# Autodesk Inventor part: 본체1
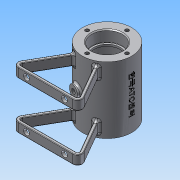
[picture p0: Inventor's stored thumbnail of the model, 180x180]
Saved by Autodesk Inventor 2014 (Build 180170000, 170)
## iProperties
Created: 2016-03
Part Number: 본체1
Material: 알루미늄 6061
Document SubType Name: Modeling
Designer: NET
Density: 2.71 g/cm^3
Appearance: 알루미늄 - 평지
Mass: 209.662 g
Surface Area: 328.168 cm^2
Volume: 77.3661 cm^3
Author: NET
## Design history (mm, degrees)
sketch "스케치1"
  geometry: C1 r 26 at (0, 0); 1 further point
  constraints: 1 centre point, 1 coincident
  dimensions: "d0" = 52 diameter of C1
extrude "돌출1" new body sketch "스케치1" stored distance "d1" = 70; taper "d2" = 0 deg
node "작업 평면2"
sketch "스케치2"
  geometry: 1 further point
sketch "스케치3"
  geometry: L1 (0, 0)-(0, -65); L2 (0, 0)-(58.644, 0); L3 (0, -65)-(-37.528, -65); L4 (-37.528, -65)-(37.528, -65); L5 (-32.332, -62)-(32.332, -62); L6 (11.547, -20)-(37.528, -65); L7 (-9.815, -23)-(-32.332, -62); L8 (32.332, -62)-(9.815, -23); L9 (-11.547, -20)-(-37.528, -65); L10 (-11.547, -20)-(11.547, -20); L11 (9.815, -23)-(-9.815, -23); C1 r 26 at (0, 0) reference; 2 further points
  constraints: 22 end point, 2 midpoint, 2 parallel, 1 horizontal, 1 point on line, 1 vertical
  dimensions: "d4" = 65 distance of L1.end L1.start; "d10" = 3 distance between parallel lines of L4 L5; "d13" = 3 distance between parallel lines of L11 L10; "d14" = 3 distance between parallel lines of L6 L8; "d15" = 3 distance between parallel lines of L9 L7; "d16" = 42 distance between parallel lines of L5 L10; "d17" = 51.96152 distance of L6.start L4.end; "d18" = 60 deg angle of L8 L7; "d19" = 75.05553 distance of L3.end L4.end
extrude "돌출2" join sketch "스케치3" distance "d20" = 10; taper "d21" = 0 deg
fillet "모깎기1" dims "d22" = 5
fillet "모깎기2" dims "d23" = 2
sketch "스케치4"
  geometry: C1 r 26 at (0, 0) reference; C2 r 16 at (0, 0)
  constraints: 1 centre point, 1 coincident
  dimensions: "d24" = 32 diameter of C2
extrude "돌출3" cut sketch "스케치4" distance "d25" = 12; taper "d26" = 0 deg
sketch "스케치5"
  geometry: C1 r 16 at (0, 0) reference; C2 r 14 at (0, 0)
  constraints: 1 centre point, 1 coincident
  dimensions: "d27" = 28 diameter of C2
extrude "돌출4" cut sketch "스케치5" distance "d28" = 2; taper "d29" = 0 deg
node "작업 평면4"
fillet "모깎기3" dims "d33" = 0.3
node "작업 평면5"
sketch "스케치7"
  geometry: C1 r 21 at (0, 0); 1 further point
  constraints: 1 centre point, 1 coincident
  dimensions: "d37" = 42 diameter of C1
extrude "돌출6" cut sketch "스케치7" stored distance "d38" = 42; taper "d39" = 0 deg
fillet "모깎기7" dims "d40" = 3
fillet "모깎기8" dims "d41" = 0.3
node "작업 평면6"
sketch "스케치8"
  geometry: C1 r 5 at (0, 0); 1 further point
  constraints: 1 centre point, 1 coincident
  dimensions: "d43" = 10 diameter of C1
extrude "돌출7" join sketch "스케치8" stored distance "d44" = 42; taper "d45" = 0 deg
sketch "스케치9"
  geometry: L1 (0, 0)-(7.506, -28.012); L2 (0, 0)-(0, -26); 2 further points
  constraints: 4 end point, 1 coincident, 1 vertical, 1 vertical alignment, 1 other
  dimensions: "d46" = 15 deg angle of L1 L2; "d47" = 29 distance of L1.start L1.end
node "작업 평면7"
sketch "스케치10"
  geometry: C1 r 6 at (0, 0); 1 further point
  constraints: 1 centre point, 1 coincident
  dimensions: "d48" = 12 diameter of C1
extrude "돌출8" join sketch "스케치10" stored distance "d49" = 42; taper "d50" = 0 deg
hole "구멍1" diameter "d53" = 5.188; stored, may be unused: countersink angle "d57" = 90 deg, drill point angle "d59" = 118 deg; dims "d51" = 10, "d52" = 10, "d54" = 10, "d55" = 4, "d56" = 2, "d58" = 10
hole "구멍2" diameter "d62" = 5.188; stored, may be unused: countersink angle "d66" = 90 deg, drill point angle "d68" = 118 deg; dims "d60" = 10, "d61" = 10, "d63" = 10, "d64" = 4, "d65" = 2, "d67" = 10
fillet "모깎기9" dims "d69" = 2
fillet "모깎기10" dims "d70" = 2
fillet "모깎기11" dims "d71" = 2
fillet "모깎기12" dims "d72" = 5
sketch "스케치11"
  geometry: L1 (0, 0)-(57.735, 0) reference; L2 (57.735, 10)-(0, 10) reference; L3 (28.868, 10)-(28.868, 0); C1 r 3 at (8.868, 5); C2 r 3 at (48.868, 5); 1 further point
  constraints: 2 centre point, 2 end point, 2 midpoint, 1 horizontal alignment
  dimensions: "d73" = 6 diameter of C1; "d74" = 6 diameter of C2; "d75" = 20 distance from line of C1.centre L3; "d76" = 40 distance of C2.centre C1.centre; "d77" = 5 distance from line of L1 C1.centre
extrude "돌출9" cut sketch "스케치11" distance "d78" = 42; taper "d79" = 0 deg
node "작업 평면8"
sketch "스케치12"
  geometry: L1 (26, 35)-(-26, 35) reference; 2 further points
  constraints: 1 coincident, 1 other
feature "엠보싱1" sketch "스케치12" dims "d82" = 0.5, "d83" = 0
chamfer "모따기1" distance "d84" = 1; stored, may be unused: second distance "d85" = 2, angle "d86" = 45 deg
chamfer "모따기2" distance "d87" = 1; stored, may be unused: second distance "d88" = 2, angle "d89" = 45 deg
sketch "스케치13" dims "d91" = 42
  geometry: L1 (0, 21)-(0, 0); C1 r 17 at (0, 0) reference; 1 further point
  constraints: 2 coincident, 2 end point, 1 vertical, 1 vertical alignment, 2 other
hole "구멍3" sketch "스케치13" at (0, 21) diameter "d92" = 4; stored, may be unused: countersink angle "d96" = 90 deg, drill point angle "d98" = 118 deg; dims "d93" = 6, "d94" = 4, "d95" = 2, "d97" = 10
feature "스레드1" dims "d99" = 8, "d100" = 0
feature "스레드2" dims "d104" = 8, "d105" = 0
fillet "모깎기13" dims "d109" = 0.5
fillet "모깎기14" dims "d110" = 0.5
fillet "모깎기15" dims "d111" = 3
node "솔리드1"
mirror "대칭4"
mirror "대칭5"
pattern_circular "원형 패턴1" dims angle "d102" = 360 deg
mirror "대칭6"
pattern_circular "원형 패턴2" dims "d107" = 360 deg
other parameters: "d6" = 30 deg, "d7" = 30 deg, "d8" = 3, "d9" = 3, "d11" = 3, "d12" = 45, "d42" = 29, "d80" = 26
